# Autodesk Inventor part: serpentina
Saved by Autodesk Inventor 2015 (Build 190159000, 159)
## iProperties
Created: 2015-06
Part Number: serpentina
Material: Generic
Document SubType Name: Modeling
Designer: Franzi-CAD
Density: 1 g/cm^3
Appearance: 166,83,0
Translation Standard: IGES 5.3
FileName: 1 Sistema de RefrigeraÃ§Ã£o Industrial - 3D v3
PreProcessor: AutoCAD 2015 - English
PostProcessor: Build: 160, Release: 2012 RTM - Date: Tue 03/01/2011
Sent Units: millimeter
Uncertainty: 0.01
Author: Franzi-CAD
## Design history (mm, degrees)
node "serpentina1"
node "1 Sistema de Refrigeração Industrial - 3D v3"
node "1 Sistema de Refrigeração Industrial - 3D v3_1"
node "1 Sistema de Refrigeração Industrial - 3D v3_2"
node "1 Sistema de Refrigeração Industrial - 3D v3_3"
node "1 Sistema de Refrigeração Industrial - 3D v3_4"
node "1 Sistema de Refrigeração Industrial - 3D v3_5"
node "1 Sistema de Refrigeração Industrial - 3D v3_6"
node "1 Sistema de Refrigeração Industrial - 3D v3_7"
node "1 Sistema de Refrigeração Industrial - 3D v3_8"
node "1 Sistema de Refrigeração Industrial - 3D v3_9"
node "1 Sistema de Refrigeração Industrial - 3D v3_10"
node "1 Sistema de Refrigeração Industrial - 3D v3_11"
node "1 Sistema de Refrigeração Industrial - 3D v3_12"
node "1 Sistema de Refrigeração Industrial - 3D v3_13"
node "1 Sistema de Refrigeração Industrial - 3D v3_14"
node "1 Sistema de Refrigeração Industrial - 3D v3_15"
node "1 Sistema de Refrigeração Industrial - 3D v3_16"
node "1 Sistema de Refrigeração Industrial - 3D v3_17"
node "1 Sistema de Refrigeração Industrial - 3D v3_18"
node "1 Sistema de Refrigeração Industrial - 3D v3_19"
node "1 Sistema de Refrigeração Industrial - 3D v3_20"
node "1 Sistema de Refrigeração Industrial - 3D v3_21"
node "1 Sistema de Refrigeração Industrial - 3D v3_22"
node "1 Sistema de Refrigeração Industrial - 3D v3_23"
node "1 Sistema de Refrigeração Industrial - 3D v3_24"
node "1 Sistema de Refrigeração Industrial - 3D v3_25"
node "1 Sistema de Refrigeração Industrial - 3D v3_26"
node "1 Sistema de Refrigeração Industrial - 3D v3_27"
node "1 Sistema de Refrigeração Industrial - 3D v3_28"
node "1 Sistema de Refrigeração Industrial - 3D v3_29"
node "1 Sistema de Refrigeração Industrial - 3D v3_30"
node "1 Sistema de Refrigeração Industrial - 3D v3_31"
node "1 Sistema de Refrigeração Industrial - 3D v3_32"
node "1 Sistema de Refrigeração Industrial - 3D v3_33"
node "1 Sistema de Refrigeração Industrial - 3D v3_34"
node "1 Sistema de Refrigeração Industrial - 3D v3_35"
node "1 Sistema de Refrigeração Industrial - 3D v3_36"
node "1 Sistema de Refrigeração Industrial - 3D v3_37"
node "1 Sistema de Refrigeração Industrial - 3D v3_38"
node "1 Sistema de Refrigeração Industrial - 3D v3_39"
node "1 Sistema de Refrigeração Industrial - 3D v3_40"
node "1 Sistema de Refrigeração Industrial - 3D v3_41"
node "1 Sistema de Refrigeração Industrial - 3D v3_42"
node "Base1"
node "Base2"
node "Base3"
node "Base4"
node "Base5"
node "Base6"
node "Base7"
node "Base8"
node "Base9"
node "Base10"
node "Base11"
node "Base12"
node "Base13"
node "Base14"
node "Base15"
node "Base16"
node "Base17"
node "Base18"
node "Base19"
node "Base20"
node "Base21"
node "Base22"
node "Base23"
node "Base24"
node "Base25"
node "Base26"
node "Base27"
node "Base28"
node "Base29"
node "Base30"
node "Base31"
node "Base32"
node "Base33"
node "Base34"
node "Base35"
node "Base36"
node "Base37"
node "Base38"
node "Base39"
node "Base40"
node "Base41"
node "Base42"
node "Base43"
